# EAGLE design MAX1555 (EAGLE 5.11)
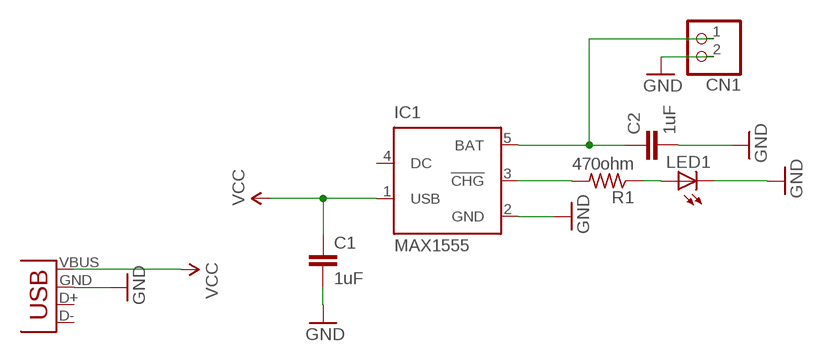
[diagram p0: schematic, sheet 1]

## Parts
C1  1uF  CAPPTH  [CAP-PTH-SMALL]
C2  1uF  CAPPTH  [CAP-PTH-SMALL]
CN1  JST_2PIN-THM  [JST-PH-2-THM]
IC1  MAX1555  [SOT23-5L]
LED1  LEDCHIP-LED0805  [CHIP-LED0805]
R1  470ohm  FLIPFLOP-RES  [0805-THM]
X1  USB-A-H  [USB-A-H]

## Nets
GND: C1.2 C2.2 CN1.2 IC1.2(GND) LED1.C X1.GND(VBUS)
N$1: IC1.3(!CHG) R1.2
N$2: LED1.A R1.1
N$5: C2.1 CN1.1 IC1.5(BAT)
VCC: C1.1 IC1.1(USB) X1.VBUS(GND)
Unconnected: IC1.4(DC) X1.D+(D-) X1.D-(D+)

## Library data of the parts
C1 C2 = SparkFun:CAP: Capacitor
CN1 = adafruit:JST_2PIN: JST 2-Pin Connectors of various flavors
IC1 = maxim:MAX1555: Dual-Input USB/AC Adapter 1-Cell Li+ Battery Chargers Source: http://www.maxim-ic.com .. MAX1551-MAX1555.pdf; MF: MAXIM; MPN: MAX1555EZK+T; OC_FARNELL: 1628222; OC_NEWARK: 59J2761
LED1 = adafruit:LED: LED
R1 = adafruit:FLIPFLOP-RES: Flip Flop resistor
X1 = SparkFun:USB: USB Connectors USB-B-PTH is fully proven SKU : PRT-00139 USB-miniB is fully proven SKU : PRT-00587 USB-A-PCB is untested. USB-A-H is throughly reviewed, but untested. Spark Fun Electronics SKU : PRT-00437 USB-B-SMT is throughly reviewed, but untested. Needs silkscreen touching up. USB-A-S has not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

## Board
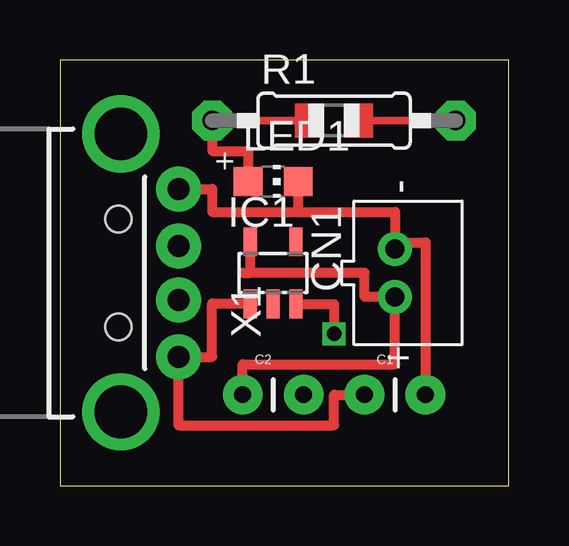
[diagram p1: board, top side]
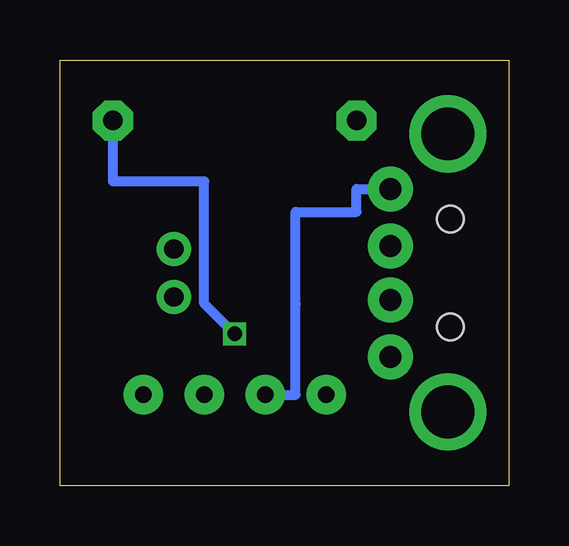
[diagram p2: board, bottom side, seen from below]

Size 18.72 x 17.77 mm. Coordinates in mm from the lower left corner, seen from the top.
Outline: 0,0 18.72,0 18.72,17.77 0,17.77 0,0
Copper layers (1*16): Top 0.0356mm / dielectric 1.5011mm / Bottom 0.0356mm
Design rules "Dorkbot-PDX": minimum track width 6mil, minimum drill 13mil, track to track 6mil, track to pad 6mil, pad to pad 6mil, via to via 6mil, smd to smd 6mil, copper to edge 15mil, drill to drill 6mil, minimum pad ring 7mil, minimum via ring 7mil, stop-mask expansion 4mil, vias tented up to drill 0mil, thermal gap 10mil

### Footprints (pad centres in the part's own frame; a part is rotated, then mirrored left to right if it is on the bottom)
CAP-PTH-SMALL = drill 0.7 pad 1.651 round: 1 0,0; 2 2.54,0
JST-PH-2-THM = drill 0.8 pad 1.422 round: 1 1,0; 2 -1,0
SOT23-5L = smd 0.55 x 1.2: 1 -0.95,-1.3; 2 0,-1.3; 3 0.95,-1.3; 4 0.95,1.3; 5 -0.95,1.3
CHIP-LED0805 = smd 1.2 x 1.2: A 0,-1.05; C 0,1.05
0805-THM = drill 0.813 pad 1.676 octagon: 1 -5.08,0; 2 5.08,0
USB-A-H = drill 0.914 pad 1.88 round: D+ 2.4,1.127; D- 2.4,-1.127; GND 2.4,3.5; VBUS 2.4,-3.5 | drill 2.2 round: GND@1 0,5.8; GND@2 0,-5.8 | hole 1.1: -0.1,2.25; -0.1,-2.25

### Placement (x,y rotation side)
C1  12.7,3.81 0 top
C2  7.62,3.81 0 top
CN1  13.97,8.89 270 top
IC1  8.89,8.89 0 top
LED1  8.89,12.7 270 top
R1  11.43,15.24 0 top
X1  2.54,8.89 0 top

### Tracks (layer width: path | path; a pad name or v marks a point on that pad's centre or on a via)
GND  (1 unrouted)
  Top 0.406: X1.GND 6.35,12.39 6.35,11.43 9.94,11.43 | 9.94,11.43 LED1.C | 9.94,11.43 13.97,11.43 CN1.2 13.97,10.16 15.24,10.16 C1.2
  Bottom 0.406: C2.2 8.89,3.81 IC1.2 8.89,11.43 6.35,11.43 6.35,12.39 X1.GND
N$1  (via drill 0.6)
  Top 0.406: IC1.3 11.43,7.59 v11.43,6.35
  Bottom 0.406: v11.43,6.35 12.7,7.62 12.7,12.7 16.51,12.7 R1.2
N$2
  Top 0.406: R1.1 6.35,13.97 7.84,13.97 LED1.A
N$5
  Top 0.406: C2.1 7.62,5.08 13.97,5.08 CN1.1 12.7,7.89 12.7,8.89 7.94,8.89 | 7.62,8.89 7.94,8.89 | 7.94,8.89 IC1.5
VCC
  Top 0.406: C1.1 11.43,3.81 11.43,2.54 4.94,2.54 X1.VBUS 6.35,5.39 6.35,7.62 7.94,7.62 IC1.1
